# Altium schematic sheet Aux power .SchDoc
size A3; Organization: ORGANIZATION; Address1: ADDRESS 1; Address2: ADDRESS 2; Address3: ADDRESS 3; Address4: ADDRESS 4; Revision: -; SheetNumber: 2; SheetTotal: 4; ENG_APP_DATE: --/--/--; DSN_APP_DATE: --/--/--; CHK_APP_DATE: --/--/--
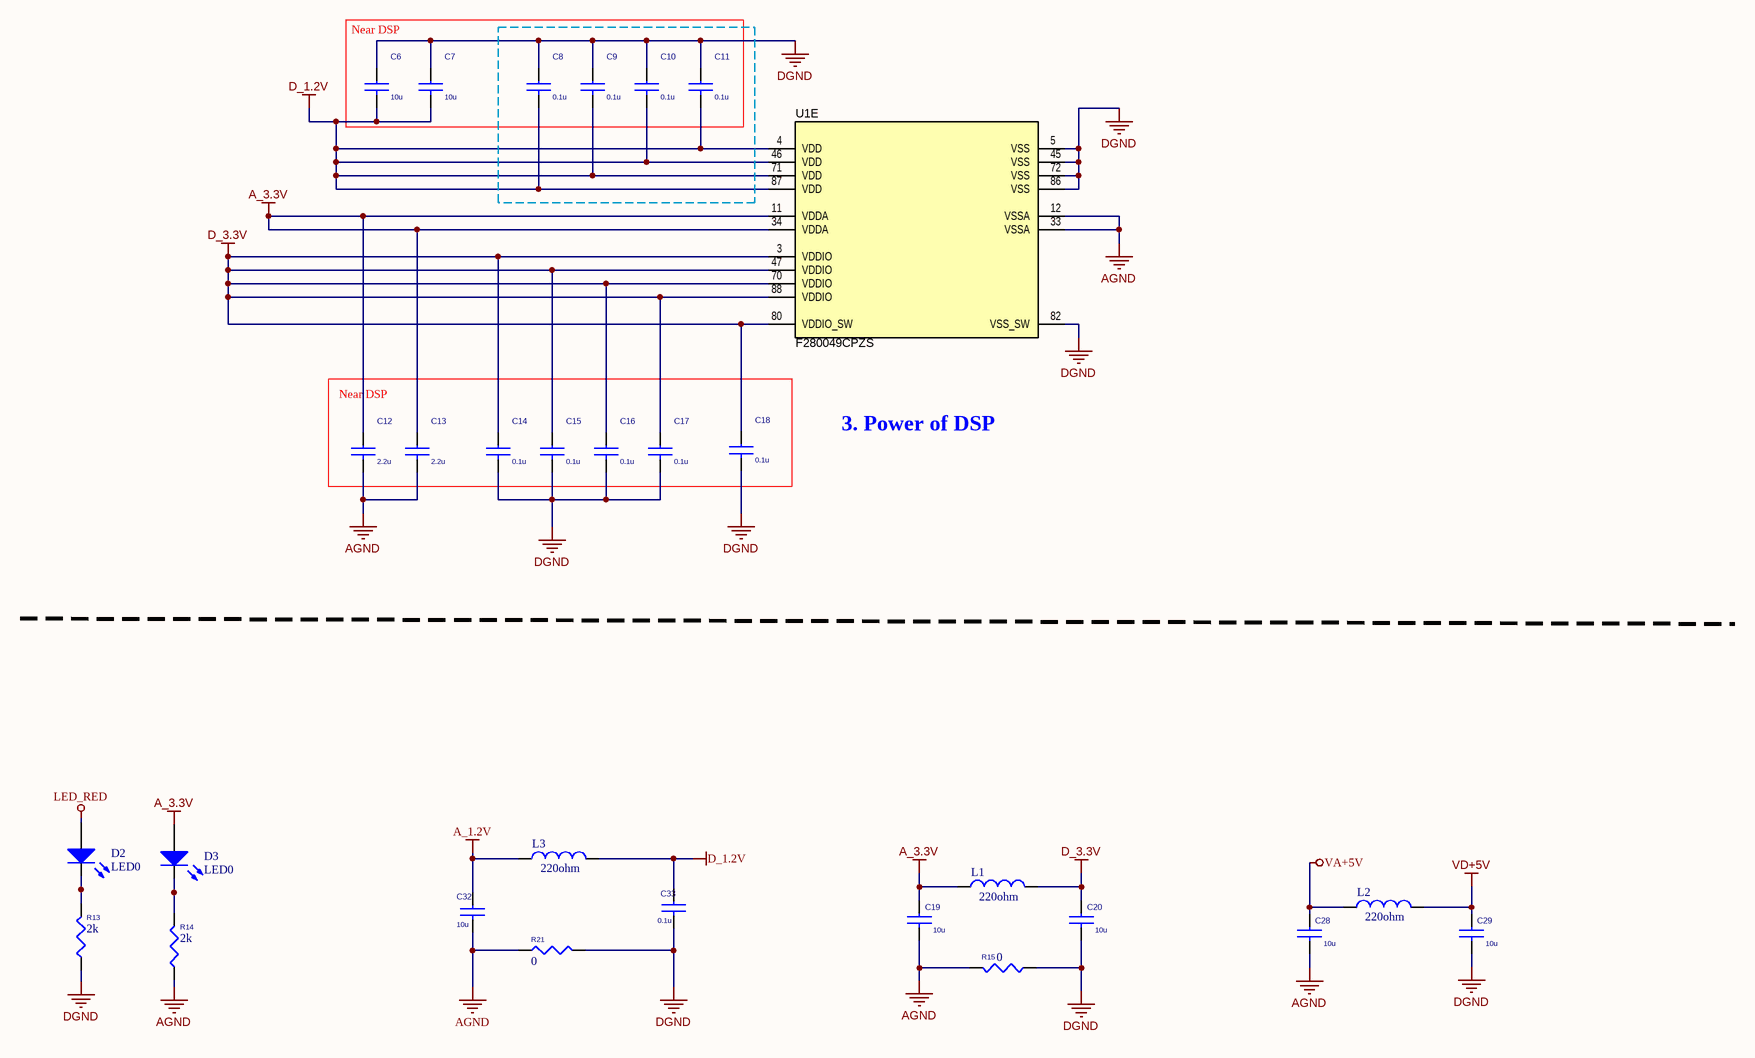
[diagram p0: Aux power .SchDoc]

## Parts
C6  10u  [C0402]
C7  10u  [C0402]
C8  0.1u  [C0402]
C9  0.1u  [C0402]
C10  0.1u  [C0402]
C11  0.1u  [C0402]
C12  2.2u  [C0402]
C13  2.2u  [C0402]
C14  0.1u  [C0402]
C15  0.1u  [C0402]
C16  0.1u  [C0402]
C17  0.1u  [C0402]
C18  0.1u  [C0402]
C19  10u  [C0402]
C20  10u  [C0402]
C28  10u  [C0402]
C29  10u  [C0402]
C32  10u  [C0402]
C33  0.1u  [C0402]
D2  LED0  [LED0805]
D3  LED0  [LED0805]
L1  value 220ohm  [6-0805_L]  (hidden comment: BLM21PG221SN1D)
L2  value 220ohm  [6-0805_L]  (hidden comment: BLM21PG221SN1D)
L3  value 220ohm  [6-0805_L]  (hidden comment: BLM21PG221SN1D)
R13  2k  [R0402]
R14  2k  [R0402]
R15  0  [R0402]
R21  0  [R0402]
U1  F280049CPZS  [PZ0100A_N]  (part E of 5)

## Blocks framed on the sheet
Near DSP: C6-C11
Near DSP: C12-C18

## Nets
A_1.2V: C32.1 L3.1
A_3.3V: C12.1 C13.1 C19.1 D3.1(A) L1.1 U1.11(VDDA) U1.34(VDDA)
AGND: C12.2 C13.2 C19.2 C28.2 C32.2 R14.1 R15.2 R21.1 U1.12(VSSA) U1.33(VSSA)
D_1.2V: C6.2 C7.2 C8.2 C9.2 C10.2 C11.2 C33.1 L3.2 U1.4(VDD) U1.46(VDD) U1.71(VDD) U1.87(VDD)
D_3.3V: C14.1 C15.1 C16.1 C17.1 C18.1 C20.1 L1.2 U1.3(VDDIO) U1.47(VDDIO) U1.70(VDDIO) U1.80(VDDIO_SW) U1.88(VDDIO)
DGND: C6.1 C7.1 C8.1 C9.1 C10.1 C11.1 C14.2 C15.2 C16.2 C17.2 C18.2 C20.2 C29.2 C33.2 R13.1 R15.1 R21.2 U1.5(VSS) U1.45(VSS) U1.72(VSS) U1.82(VSS_SW) U1.86(VSS)
LED_RED: D2.1(A)
VA+5V: C28.1 L2.1
VD+5V: C29.1 L2.2
NetD2_2: D2.2(K) R13.2
NetD3_2: D3.2(K) R14.2

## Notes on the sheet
- 3. Power of DSP

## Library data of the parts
C6 C7 C19 C20 C28 C29 C32 = CAP NP_Dup1: CAP CER 10UF 10V X5R 0402; PCB Footprint: C1206
C8-C11 C14-C18 C33 = CAP NP_Dup1: CAP CER 0.1UF 25V X7R 0402; PCB Footprint: C1206
C12 C13 = CAP NP_Dup1: CAP CER 2.2UF 25V JB 0402; PCB Footprint: C1206
D2 D3 = LED0: LED RED CLEAR 0805 SMD
L1-L3 = Inductor: FERRITE BEAD 220 OHM 0805 1LN; Code_IEC: 1005
R13 R14 = RESISTOR_Dup1: RCC0402 100 2K0 1% ET7 E3; PCB Footprint: R0603
R15 R21 = RESISTOR_Dup1: PCB Footprint: R0603
U1 = CMP-0078352-1: Piccolo Microcontroller, PZ0100A (LQFP-100); Manufacturer: Texas Instruments; SizeArea_mm2: 256; SizeAreaWB_mm2: 324; SizeX_mm: 16; SizeZ_mm: 1.6; CompType: IC; AEC Category: Q200; AEC Qualified: N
